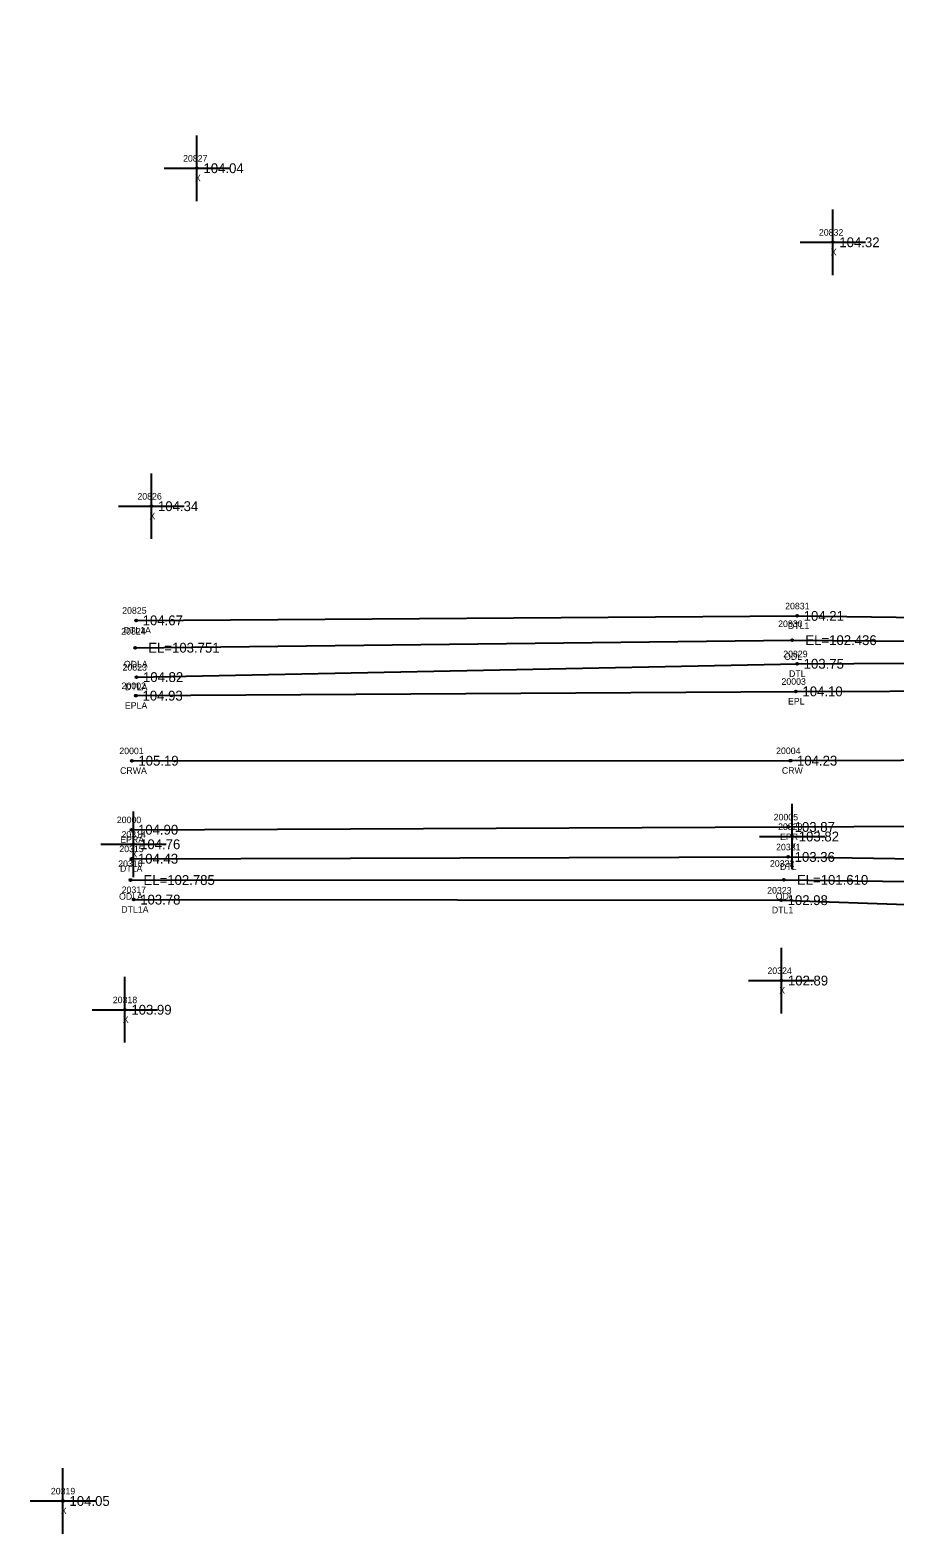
# Model space of a CAD drawing. Extents: x 2530197 to 2532051, y 935230 to 936631.
# Drawn here: x 2530197 to 2530328.9, y 935471.7 to 935701.6 of the extents above; entities that cross this region are included whole.
import ezdxf

# ---------------------------------------------------------------- set-up
doc = ezdxf.new("R2010")
doc.units = 0
for name, color, linetype in [('RD_DTM_BkLn1', 7, 'Continuous'), ('RD_EX_H2O', 7, 'Continuous'), ('RD_EX_H2O_txCode', 7, 'Continuous'), ('RD_EX_Misc', 7, 'Continuous'), ('RD_EX_Misc_txCode', 7, 'Continuous'), ('RD_EX_Road', 7, 'Continuous'), ('RD_EX_Road_txCode', 7, 'Continuous'), ('RD_EX_TX_H2O_ELEV', 7, 'Continuous'), ('RD_EX_TX_Misc_ELEV', 7, 'Continuous'), ('RD_EX_TX_Road_ELEV', 7, 'Continuous'), ('RD_HC_Survey_ELEV', 7, 'Continuous'), ('RD_HC_Survey_txCode', 7, 'Continuous'), ('RD_SMD_Locator', 7, 'Continuous')]:
    doc.layers.add(name, color=color, linetype=linetype)

msp = doc.modelspace()

# ---------------------------------------------------------------- linework, layer by layer
at = {"layer": 'RD_DTM_BkLn1'}
msp.add_lwpolyline([(2530212.5, 935590.24), (2530312.97, 935590.25), (2530414.21, 935590.57), (2530470.01, 935593.88), (2530526.51, 935611.77), (2530574.01, 935635.84), (2530615.35, 935659.73), (2530701.7, 935710.7), (2530789.3, 935762.35), (2530874.46, 935813.14), (2530961.78, 935865.4), (2531046.63, 935916.04), (2531084.76, 935938.51)], dxfattribs=at)
at = {"layer": 'RD_EX_H2O'}
for points in [[(2530213.15, 935611.64), (2530313.99, 935612.32), (2530400.87, 935611.18), (2530410.57, 935607.04)], [(2530213.01, 935607.47), (2530313.25, 935608.62), (2530400.73, 935607.92), (2530410.57, 935607.04)], [(2530213.2, 935602.99), (2530313.99, 935605.02), (2530400.59, 935605.5), (2530410.57, 935607.04)], [(2530212.43, 935575.3), (2530312.61, 935575.57), (2530413.4, 935574.03), (2530431.14, 935570.94), (2530447.74, 935563.43), (2530459.72, 935547.88), (2530491.74, 935452.52), (2530522.77, 935357.57), (2530554.82, 935263)], [(2530212.28, 935572.05), (2530311.96, 935572.07), (2530413.48, 935570.72), (2530429.97, 935567.74), (2530445.97, 935560.86), (2530457.18, 935547.13), (2530489.52, 935451.8), (2530520.38, 935357.21), (2530552.97, 935262.56)], [(2530212.78, 935569.06), (2530311.54, 935568.98), (2530412.57, 935565.49), (2530428.32, 935562.93), (2530442.59, 935555.84), (2530453.4, 935544.85), (2530485.1, 935450.23), (2530516.56, 935356.42), (2530549.63, 935261.88)]]:
    msp.add_lwpolyline(points, dxfattribs=at)
at = {"layer": 'RD_EX_Misc'}
for p, q in [((2530222.43, 935675.58), (2530222.43, 935685.58)), ((2530217.43, 935680.58), (2530227.43, 935680.58)), ((2530319.43, 935664.29), (2530319.43, 935674.29)), ((2530314.43, 935669.29), (2530324.43, 935669.29)), ((2530215.49, 935624.05), (2530215.49, 935634.05)), ((2530210.49, 935629.05), (2530220.49, 935629.05)), ((2530212.76, 935572.5), (2530212.76, 935582.5)), ((2530313.24, 935573.68), (2530313.24, 935583.68)), ((2530207.76, 935577.5), (2530217.76, 935577.5)), ((2530308.24, 935578.68), (2530318.24, 935578.68)), ((2530311.58, 935551.72), (2530311.58, 935561.72)), ((2530211.43, 935547.27), (2530211.43, 935557.27)), ((2530306.58, 935556.72), (2530316.58, 935556.72)), ((2530206.43, 935552.27), (2530216.43, 935552.27)), ((2530201.99, 935472.37), (2530201.99, 935482.37)), ((2530196.99, 935477.37), (2530206.99, 935477.37))]:
    msp.add_line(p, q, dxfattribs=at)
at = {"layer": 'RD_EX_Road'}
for points in [[(2530213.13, 935600.16), (2530313.8, 935600.81), (2530414.15, 935601.13), (2530426.72, 935601.43), (2530429.46, 935603.55), (2530467.67, 935608.62), (2530486.46, 935612.38), (2530518.02, 935622.55), (2530522.16, 935623.68), (2530567.91, 935646.01), (2530609.3, 935670.15), (2530695.46, 935720.02), (2530775.85, 935769.27), (2530868.29, 935824.03), (2530924.84, 935856.95), (2530956.21, 935875.82), (2531040.72, 935926.38), (2531079.45, 935947.76)], [(2530212.44, 935579.72), (2530312.61, 935580.14), (2530402.98, 935580.64), (2530451.06, 935579.53), (2530466.91, 935580.35), (2530487.45, 935583.29), (2530533.43, 935598.45), (2530580.28, 935625.08), (2530621.69, 935649.23), (2530704.62, 935698.35), (2530718.67, 935706.38), (2530795.45, 935752.36), (2530871.33, 935796.67), (2530882.4, 935803.04), (2530947.17, 935842.26), (2530966, 935852.42), (2530992.72, 935868), (2531009.49, 935879.01), (2531052.39, 935904.85), (2531090.88, 935928.23)]]:
    msp.add_lwpolyline(points, dxfattribs=at)
at = {"layer": 'RD_SMD_Locator'}
for centre in [(2530222.43, 935680.58), (2530319.43, 935669.29), (2530215.49, 935629.05), (2530213.15, 935611.64), (2530313.99, 935612.32), (2530213.01, 935607.47), (2530313.25, 935608.62), (2530313.99, 935605.02), (2530213.2, 935602.99), (2530213.13, 935600.16), (2530313.8, 935600.81), (2530212.5, 935590.24), (2530312.97, 935590.25), (2530212.44, 935579.72), (2530312.61, 935580.14), (2530212.76, 935577.5), (2530313.24, 935578.68), (2530212.43, 935575.3), (2530312.61, 935575.57), (2530212.28, 935572.05), (2530311.96, 935572.07), (2530212.78, 935569.06), (2530311.54, 935568.98), (2530311.58, 935556.72), (2530211.43, 935552.27), (2530201.99, 935477.37)]:
    msp.add_circle(centre, 0.15, dxfattribs=at)

# ---------------------------------------------------------------- texts
at = {"layer": 'RD_EX_H2O_txCode'}
for s, p in [('20831', (2530312.16, 935613.32)), ('20825', (2530211.03, 935612.64)), ('20824', (2530210.89, 935609.47)), ('DTL1A', (2530211.25, 935609.64)), ('20830', (2530311.09, 935610.62)), ('DTL1', (2530312.58, 935610.32)), ('20823', (2530211.08, 935603.99)), ('ODLA', (2530211.28, 935604.47)), ('20829', (2530311.87, 935606.02)), ('ODL', (2530312, 935605.62)), ('DTL', (2530312.75, 935603.02)), ('DTLA', (2530211.47, 935600.99)), ('20315', (2530210.59, 935576.3)), ('20321', (2530310.78, 935576.57)), ('20316', (2530210.42, 935574.05)), ('20322', (2530309.84, 935574.07)), ('DTLA', (2530210.69, 935573.3)), ('DTL', (2530311.37, 935573.57)), ('20317', (2530210.95, 935570.06)), ('20323', (2530309.42, 935569.98)), ('ODLA', (2530210.55, 935569.05)), ('ODL', (2530310.72, 935569.07)), ('DTL1A', (2530210.89, 935567.06)), ('DTL1', (2530310.13, 935566.98))]:
    msp.add_text(s, height=1, dxfattribs=at).set_placement(p)
at = {"layer": 'RD_EX_Misc_txCode'}
for s, p in [('20827', (2530220.32, 935681.58)), ('X', (2530222.12, 935678.58)), ('20832', (2530317.31, 935670.29)), ('X', (2530319.11, 935667.29)), ('20826', (2530213.35, 935630.05)), ('X', (2530215.18, 935627.05)), ('20320', (2530311.08, 935579.68)), ('20314', (2530210.92, 935578.5)), ('X', (2530312.93, 935576.68)), ('X', (2530212.44, 935575.5)), ('20324', (2530309.46, 935557.72)), ('X', (2530311.26, 935554.72)), ('20318', (2530209.6, 935553.27)), ('X', (2530211.12, 935550.27)), ('20319', (2530200.15, 935478.37)), ('X', (2530201.67, 935475.37))]:
    msp.add_text(s, height=1, dxfattribs=at).set_placement(p)
at = {"layer": 'RD_EX_Road_txCode'}
for s, p in [('20003', (2530311.6, 935601.81)), ('20002', (2530210.93, 935601.16)), ('EPLA', (2530211.44, 935598.16)), ('EPL', (2530312.59, 935598.81)), ('20005', (2530310.41, 935581.14)), ('20000', (2530210.21, 935580.72)), ('EPRA', (2530210.73, 935577.72)), ('EPR', (2530311.38, 935578.14))]:
    msp.add_text(s, height=1, dxfattribs=at).set_placement(p)
at = {"layer": 'RD_EX_TX_H2O_ELEV'}
for s, p in [('104.67', (2530214.15, 935610.89)), ('104.21', (2530314.99, 935611.57)), ('EL=103.751', (2530215.01, 935606.72)), ('EL=102.436', (2530315.25, 935607.87)), ('103.75', (2530314.99, 935604.27)), ('104.82', (2530214.2, 935602.24)), ('104.43', (2530213.43, 935574.55)), ('103.36', (2530313.61, 935574.82)), ('EL=102.785', (2530214.28, 935571.3)), ('EL=101.610', (2530313.96, 935571.32)), ('103.78', (2530213.78, 935568.31)), ('102.98', (2530312.54, 935568.23))]:
    msp.add_text(s, height=1.5, dxfattribs=at).set_placement(p)
at = {"layer": 'RD_EX_TX_Misc_ELEV'}
for s, p in [('104.04', (2530223.43, 935679.83)), ('104.32', (2530320.43, 935668.54)), ('104.34', (2530216.49, 935628.3)), ('104.76', (2530213.76, 935576.75)), ('103.82', (2530314.24, 935577.93)), ('102.89', (2530312.58, 935555.97)), ('103.99', (2530212.43, 935551.52)), ('104.05', (2530202.99, 935476.62))]:
    msp.add_text(s, height=1.5, dxfattribs=at).set_placement(p)
at = {"layer": 'RD_EX_TX_Road_ELEV'}
for s, p in [('104.93', (2530214.13, 935599.41)), ('104.10', (2530314.8, 935600.06)), ('104.90', (2530213.44, 935578.97)), ('103.87', (2530313.61, 935579.39))]:
    msp.add_text(s, height=1.5, dxfattribs=at).set_placement(p)
at = {"layer": 'RD_HC_Survey_ELEV'}
for s, p in [('105.19', (2530213.5, 935589.49)), ('104.23', (2530313.97, 935589.5))]:
    msp.add_text(s, height=1.5, dxfattribs=at).set_placement(p)
at = {"layer": 'RD_HC_Survey_txCode'}
for s, p in [('20001', (2530210.59, 935591.24)), ('20004', (2530310.78, 935591.25)), ('CRWA', (2530210.7, 935588.24)), ('CRW', (2530311.66, 935588.25))]:
    msp.add_text(s, height=1, dxfattribs=at).set_placement(p)

doc.saveas('drawing.dxf')
